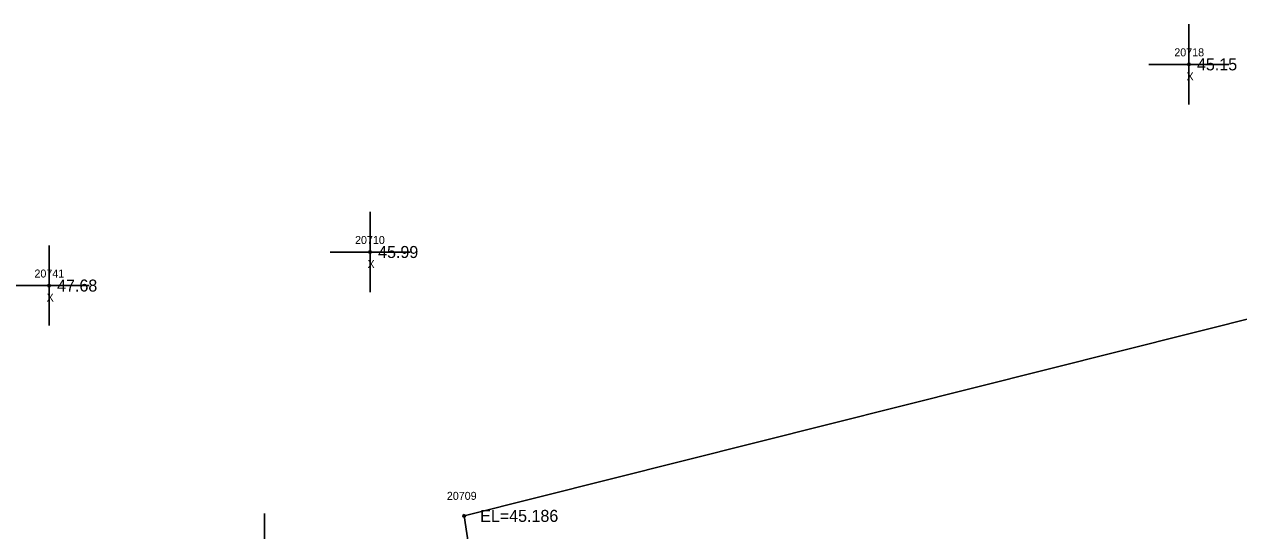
# Model space of a CAD drawing. Extents: x 2420351 to 2422725, y 845330 to 846558.
# Drawn here: x 2421635.3 to 2421787.1, y 846031.6 to 846094.9 of the extents above; entities that cross this region are included whole.
import ezdxf

# ---------------------------------------------------------------- set-up
doc = ezdxf.new("R2010")
doc.units = 0
for name, color, linetype in [('RD_EX_H2O', 7, 'Continuous'), ('RD_EX_H2O_txCode', 7, 'Continuous'), ('RD_EX_Misc', 7, 'Continuous'), ('RD_EX_Misc_txCode', 7, 'Continuous'), ('RD_EX_TX_H2O_ELEV', 7, 'Continuous'), ('RD_EX_TX_Misc_ELEV', 7, 'Continuous'), ('RD_SMD_Locator', 7, 'Continuous')]:
    doc.layers.add(name, color=color, linetype=linetype)

msp = doc.modelspace()

# ---------------------------------------------------------------- linework, layer by layer
at = {"layer": 'RD_EX_H2O'}
msp.add_lwpolyline([(2421789.64, 845837.83), (2421782.25, 845842.65), (2421762.14, 845838.6), (2421745.54, 845847.69), (2421715.82, 845873.29), (2421690.16, 845897.6), (2421662.52, 845937.52), (2421691.81, 845952.74), (2421695.52, 845998.98), (2421690.3, 846033.46), (2421790.46, 846058.61), (2421873.55, 846071.45), (2421916.6, 846080.01)], dxfattribs=at)
at = {"layer": 'RD_EX_Misc'}
for p, q in [((2421780.85, 846084.86), (2421780.85, 846094.86)), ((2421775.85, 846089.86), (2421785.85, 846089.86)), ((2421678.55, 846061.42), (2421678.55, 846071.42)), ((2421638.45, 846057.23), (2421638.45, 846067.23)), ((2421673.55, 846066.42), (2421683.55, 846066.42)), ((2421633.45, 846062.23), (2421643.45, 846062.23)), ((2421665.35, 846023.75), (2421665.35, 846033.75))]:
    msp.add_line(p, q, dxfattribs=at)
at = {"layer": 'RD_SMD_Locator'}
for centre in [(2421780.85, 846089.86), (2421678.55, 846066.42), (2421638.45, 846062.23), (2421690.3, 846033.46)]:
    msp.add_circle(centre, 0.15, dxfattribs=at)

# ---------------------------------------------------------------- texts
at = {"layer": 'RD_EX_H2O_txCode'}
msp.add_text('20709', height=1, dxfattribs=at).set_placement((2421688.14, 846035.46))
at = {"layer": 'RD_EX_Misc_txCode'}
for s, p in [('20718', (2421779.02, 846090.86)), ('X', (2421780.54, 846087.86)), ('20710', (2421676.67, 846067.42)), ('20741', (2421636.62, 846063.23)), ('X', (2421678.23, 846064.42)), ('X', (2421638.14, 846060.23))]:
    msp.add_text(s, height=1, dxfattribs=at).set_placement(p)
at = {"layer": 'RD_EX_TX_H2O_ELEV'}
msp.add_text('EL=45.186', height=1.5, dxfattribs=at).set_placement((2421692.3, 846032.71))
at = {"layer": 'RD_EX_TX_Misc_ELEV'}
for s, p in [('45.15', (2421781.85, 846089.11)), ('45.99', (2421679.55, 846065.67)), ('47.68', (2421639.45, 846061.48))]:
    msp.add_text(s, height=1.5, dxfattribs=at).set_placement(p)

doc.saveas('drawing.dxf')
